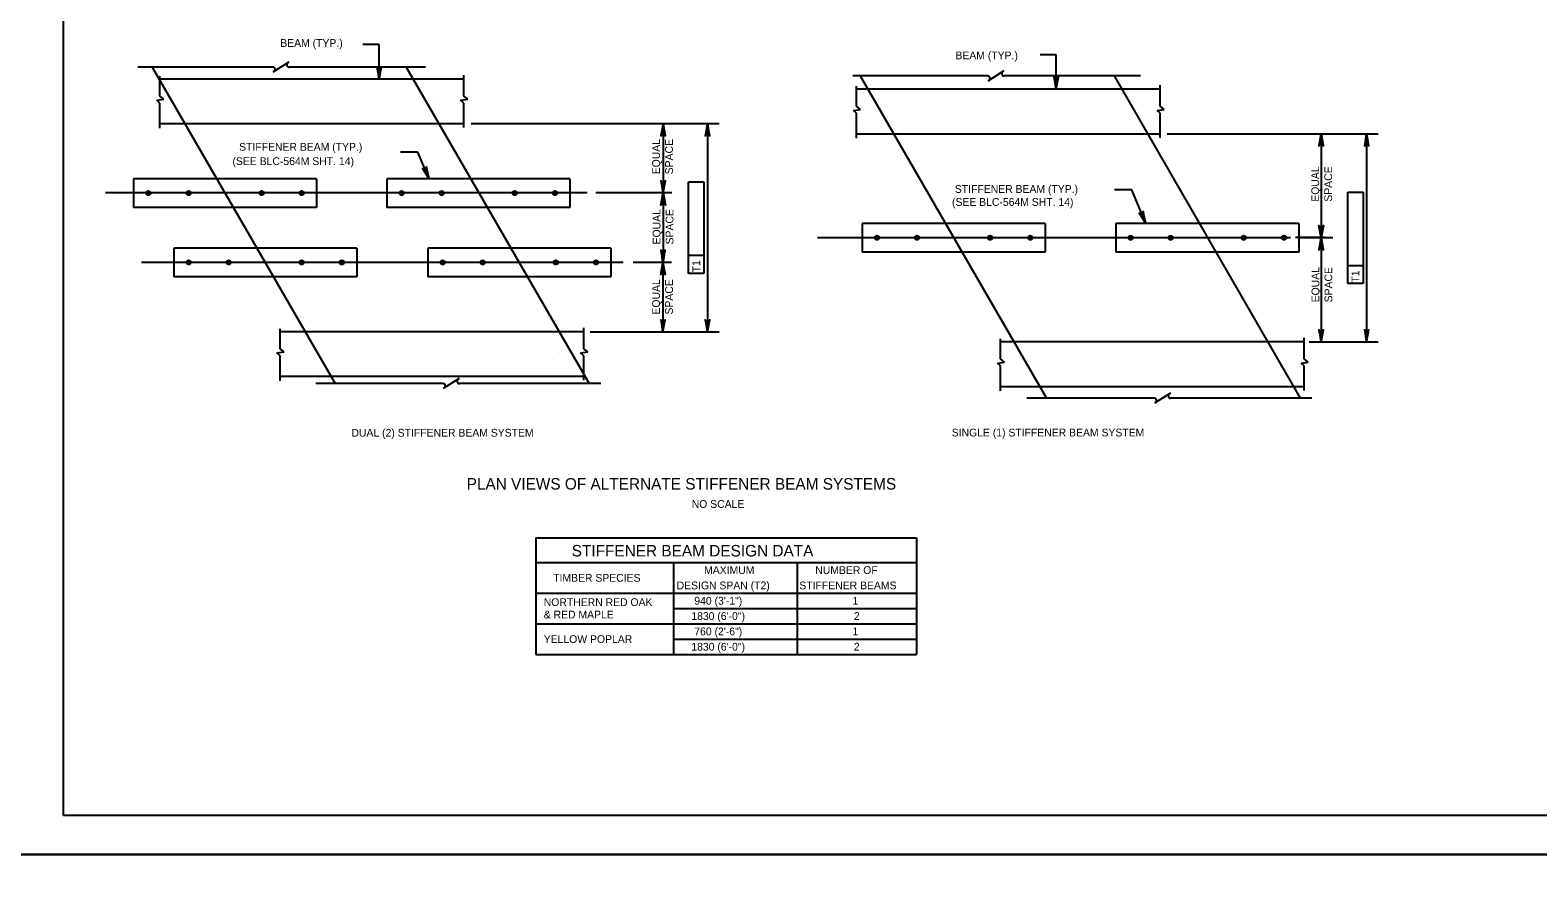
# Model space of a CAD drawing. Extents: x 638175 to 640495, y 294277 to 298435.
# Drawn here: x 639304 to 639885, y 294864 to 295189 of the extents above; entities that cross this region are included whole.
import ezdxf

# ---------------------------------------------------------------- set-up
doc = ezdxf.new("R2010")
doc.units = 0
for name, color, linetype in [('10', 7, 'Continuous'), ('2', 7, 'Continuous'), ('3', 7, 'Continuous'), ('4', 7, 'Continuous'), ('8', 7, 'Continuous'), ('PLT-BNDY', 7, 'Continuous')]:
    doc.layers.add(name, color=color, linetype=linetype)

msp = doc.modelspace()

# ---------------------------------------------------------------- linework, layer by layer
at = {"layer": '10'}
for p, q in [((639498.49, 294993.49), (639498.49, 294948.52)), ((639498.49, 294993.49), (639645.13, 294993.49)), ((639645.13, 294993.49), (639645.13, 294948.52)), ((639498.49, 294983.95), (639645.13, 294983.95)), ((639551.47, 294983.95), (639551.47, 294948.52)), ((639599.24, 294983.95), (639599.24, 294948.52)), ((639498.49, 294972.14), (639645.13, 294972.14)), ((639551.47, 294966.23), (639645.13, 294966.23)), ((639498.49, 294960.33), (639645.13, 294960.33)), ((639551.47, 294954.42), (639645.13, 294954.42)), ((639498.49, 294948.52), (639645.13, 294948.52))]:
    msp.add_line(p, q, dxfattribs=at)
at = {"layer": '2'}
for p, q in [((639316.46, 294886.46), (639316.46, 295450.46)), ((639350.66, 295174.87), (639421.15, 295052.92)), ((639448.49, 295174.87), (639518.98, 295052.92)), ((639623.5, 295171.46), (639695.29, 295047.27)), ((639721.34, 295171.46), (639793.12, 295047.27)), ((640102.46, 294886.46), (639316.46, 294886.46))]:
    msp.add_line(p, q, dxfattribs=at)
at = {"layer": '3'}
for p, q in [((639397.16, 295174.87), (639345.09, 295174.87)), ((639353.61, 295163.71), (639353.61, 295171.43)), ((639403.31, 295176.81), (639397.15, 295172.94)), ((639455.91, 295174.87), (639403.38, 295174.87)), ((639470.69, 295163.71), (639470.69, 295171.81)), ((639672.71, 295171.46), (639620.63, 295171.46)), ((639678.85, 295173.4), (639672.69, 295169.52)), ((639731.46, 295171.46), (639678.92, 295171.46)), ((639470.69, 295170.24), (639353.61, 295170.24)), ((639622.07, 295159.79), (639622.07, 295167.51)), ((639739.15, 295166.32), (639622.07, 295166.32)), ((639739.15, 295159.79), (639739.15, 295167.88)), ((639352.39, 295162.1), (639355.15, 295162.52)), ((639353.61, 295161), (639352.39, 295162.1)), ((639355.15, 295162.52), (639353.61, 295163.71)), ((639353.61, 295151.39), (639353.61, 295161)), ((639469.47, 295162.1), (639472.23, 295162.52)), ((639470.69, 295161), (639469.47, 295162.1)), ((639472.23, 295162.52), (639470.69, 295163.71)), ((639470.69, 295151.58), (639470.69, 295161)), ((639623.62, 295158.6), (639622.07, 295159.79)), ((639740.69, 295158.6), (639739.15, 295159.79)), ((639620.86, 295158.17), (639623.62, 295158.6)), ((639622.07, 295157.08), (639620.86, 295158.17)), ((639622.07, 295147.47), (639622.07, 295157.08)), ((639737.93, 295158.17), (639740.69, 295158.6)), ((639739.15, 295157.08), (639737.93, 295158.17)), ((639739.15, 295147.66), (639739.15, 295157.08)), ((639353.61, 295153.12), (639470.69, 295153.12)), ((639622.07, 295149.2), (639739.15, 295149.2)), ((639413.98, 295131.85), (639343.41, 295131.85)), ((639343.41, 295131.85), (639343.41, 295120.83)), ((639413.98, 295131.85), (639413.98, 295120.83)), ((639511.57, 295131.85), (639441, 295131.85)), ((639441, 295131.85), (639441, 295120.83)), ((639511.57, 295131.85), (639511.57, 295120.83)), ((639476.37, 295126.37), (639476.37, 295126.37)), ((639413.98, 295120.83), (639343.41, 295120.83)), ((639511.57, 295120.83), (639441, 295120.83)), ((639694.8, 295114.65), (639624.22, 295114.65)), ((639624.22, 295114.65), (639624.22, 295103.62)), ((639694.8, 295114.65), (639694.8, 295103.62)), ((639721.97, 295114.65), (639721.97, 295103.62)), ((639792.54, 295114.65), (639721.97, 295114.65)), ((639792.54, 295114.65), (639792.54, 295103.62)), ((639429.46, 295105.1), (639358.89, 295105.1)), ((639358.89, 295105.1), (639358.89, 295094.07)), ((639429.46, 295105.1), (639429.46, 295094.07)), ((639456.81, 295105.1), (639456.81, 295094.07)), ((639527.38, 295105.1), (639456.81, 295105.1)), ((639527.38, 295105.1), (639527.38, 295094.07)), ((639694.8, 295103.62), (639624.22, 295103.62)), ((639792.54, 295103.62), (639721.97, 295103.62)), ((639492.18, 295099.62), (639492.18, 295099.62)), ((639429.46, 295094.07), (639358.89, 295094.07)), ((639527.38, 295094.07), (639456.81, 295094.07)), ((639399.88, 295066.33), (639399.88, 295074.05)), ((639516.96, 295072.86), (639399.88, 295072.86)), ((639516.96, 295066.33), (639516.96, 295074.43)), ((639677.58, 295062.41), (639677.58, 295070.13)), ((639794.66, 295068.94), (639677.58, 295068.94)), ((639794.66, 295062.41), (639794.66, 295070.51)), ((639398.66, 295064.71), (639401.42, 295065.14)), ((639399.88, 295063.62), (639398.66, 295064.71)), ((639401.42, 295065.14), (639399.88, 295066.33)), ((639399.88, 295054.01), (639399.88, 295063.62)), ((639515.74, 295064.71), (639518.49, 295065.14)), ((639516.96, 295063.62), (639515.74, 295064.71)), ((639518.49, 295065.14), (639516.96, 295066.33)), ((639516.96, 295054.2), (639516.96, 295063.62)), ((639676.37, 295060.79), (639679.12, 295061.22)), ((639679.12, 295061.22), (639677.58, 295062.41)), ((639793.44, 295060.79), (639796.2, 295061.22)), ((639796.2, 295061.22), (639794.66, 295062.41)), ((639399.88, 295055.74), (639516.96, 295055.74)), ((639677.58, 295059.7), (639676.37, 295060.79)), ((639677.58, 295050.09), (639677.58, 295059.7)), ((639794.66, 295059.7), (639793.44, 295060.79)), ((639794.66, 295050.28), (639794.66, 295059.7)), ((639462.78, 295052.92), (639413.63, 295052.92)), ((639468.92, 295054.86), (639462.77, 295050.99)), ((639523.48, 295052.92), (639468.99, 295052.92)), ((639677.58, 295051.82), (639794.66, 295051.82)), ((639736.92, 295047.27), (639687.77, 295047.27)), ((639743.06, 295049.21), (639736.9, 295045.34)), ((639797.62, 295047.27), (639743.13, 295047.27))]:
    msp.add_line(p, q, dxfattribs=at)
for centre, radius in [((639349.17, 295126.34), 0.833), ((639349.17, 295126.34), 0.738), ((639349.17, 295126.34), 0.625), ((639349.17, 295126.34), 0.417), ((639349.17, 295126.34), 0.208), ((639364.62, 295126.34), 0.833), ((639364.62, 295126.34), 0.738), ((639364.62, 295126.34), 0.625), ((639364.62, 295126.34), 0.417), ((639364.62, 295126.34), 0.208), ((639392.77, 295126.34), 0.833), ((639392.77, 295126.34), 0.738), ((639392.77, 295126.34), 0.625), ((639392.77, 295126.34), 0.417), ((639392.77, 295126.34), 0.208), ((639408.22, 295126.34), 0.833), ((639408.22, 295126.34), 0.738), ((639408.22, 295126.34), 0.625), ((639408.22, 295126.34), 0.417), ((639408.22, 295126.34), 0.208), ((639446.75, 295126.34), 0.833), ((639446.75, 295126.34), 0.738), ((639446.75, 295126.34), 0.625), ((639446.75, 295126.34), 0.417), ((639446.75, 295126.34), 0.208), ((639462.21, 295126.34), 0.833), ((639462.21, 295126.34), 0.738), ((639462.21, 295126.34), 0.625), ((639462.21, 295126.34), 0.417), ((639462.21, 295126.34), 0.208), ((639490.36, 295126.34), 0.833), ((639490.36, 295126.34), 0.738), ((639490.36, 295126.34), 0.625), ((639490.36, 295126.34), 0.417), ((639490.36, 295126.34), 0.208), ((639505.81, 295126.34), 0.833), ((639505.81, 295126.34), 0.738), ((639505.81, 295126.34), 0.625), ((639505.81, 295126.34), 0.417), ((639505.81, 295126.34), 0.208), ((639629.98, 295109.14), 0.833), ((639629.98, 295109.14), 0.738), ((639629.98, 295109.14), 0.625), ((639629.98, 295109.14), 0.417), ((639629.98, 295109.14), 0.208), ((639645.43, 295109.14), 0.833), ((639645.43, 295109.14), 0.738), ((639645.43, 295109.14), 0.625), ((639645.43, 295109.14), 0.417), ((639645.43, 295109.14), 0.208), ((639673.58, 295109.14), 0.833), ((639673.58, 295109.14), 0.738), ((639673.58, 295109.14), 0.625), ((639673.58, 295109.14), 0.417), ((639673.58, 295109.14), 0.208), ((639689.04, 295109.14), 0.833), ((639689.04, 295109.14), 0.738), ((639689.04, 295109.14), 0.625), ((639689.04, 295109.14), 0.417), ((639689.04, 295109.14), 0.208), ((639727.73, 295109.14), 0.833), ((639727.73, 295109.14), 0.738), ((639727.73, 295109.14), 0.625), ((639727.73, 295109.14), 0.417), ((639727.73, 295109.14), 0.208), ((639743.18, 295109.14), 0.833), ((639743.18, 295109.14), 0.738), ((639743.18, 295109.14), 0.625), ((639743.18, 295109.14), 0.417), ((639743.18, 295109.14), 0.208), ((639771.33, 295109.14), 0.833), ((639771.33, 295109.14), 0.738), ((639771.33, 295109.14), 0.625), ((639771.33, 295109.14), 0.417), ((639771.33, 295109.14), 0.208), ((639786.79, 295109.14), 0.833), ((639786.79, 295109.14), 0.738), ((639786.79, 295109.14), 0.625), ((639786.79, 295109.14), 0.417), ((639786.79, 295109.14), 0.208), ((639364.65, 295099.59), 0.833), ((639364.65, 295099.59), 0.738), ((639364.65, 295099.59), 0.625), ((639364.65, 295099.59), 0.417), ((639364.65, 295099.59), 0.208), ((639380.1, 295099.59), 0.833), ((639380.1, 295099.59), 0.738), ((639380.1, 295099.59), 0.625), ((639380.1, 295099.59), 0.417), ((639380.1, 295099.59), 0.208), ((639408.25, 295099.59), 0.833), ((639408.25, 295099.59), 0.738), ((639408.25, 295099.59), 0.625), ((639408.25, 295099.59), 0.417), ((639408.25, 295099.59), 0.208), ((639423.7, 295099.59), 0.833), ((639423.7, 295099.59), 0.738), ((639423.7, 295099.59), 0.625), ((639423.7, 295099.59), 0.417), ((639423.7, 295099.59), 0.208), ((639462.56, 295099.59), 0.833), ((639462.56, 295099.59), 0.738), ((639462.56, 295099.59), 0.625), ((639462.56, 295099.59), 0.417), ((639462.56, 295099.59), 0.208), ((639478.02, 295099.59), 0.833), ((639478.02, 295099.59), 0.738), ((639478.02, 295099.59), 0.625), ((639478.02, 295099.59), 0.417), ((639478.02, 295099.59), 0.208), ((639506.17, 295099.59), 0.833), ((639506.17, 295099.59), 0.738), ((639506.17, 295099.59), 0.625), ((639506.17, 295099.59), 0.417), ((639506.17, 295099.59), 0.208), ((639521.62, 295099.59), 0.833), ((639521.62, 295099.59), 0.738), ((639521.62, 295099.59), 0.625), ((639521.62, 295099.59), 0.417), ((639521.62, 295099.59), 0.208)]:
    msp.add_circle(centre, radius, dxfattribs=at)
for centre, start, end in [((639397.08, 295173.97), 302.13276, 84.67141), ((639403.38, 295175.78), 120, 270), ((639672.62, 295170.55), 302.13276, 84.67141), ((639678.92, 295172.37), 120, 270), ((639462.69, 295052.02), 302.13276, 84.67141), ((639468.99, 295053.83), 120, 270), ((639736.83, 295046.37), 302.13276, 84.67141), ((639743.13, 295048.18), 120, 270)]:
    msp.add_arc(centre, 0.909, start, end, dxfattribs=at)
at = {"layer": '4'}
for p, q in [((639438.1, 295183.58), (639431.85, 295183.58)), ((639699.05, 295179.66), (639692.83, 295179.66)), ((639473.5, 295153.12), (639558.68, 295153.12)), ((639530.88, 295153.12), (639569.12, 295153.12)), ((639534.7, 295153.12), (639549.76, 295153.12)), ((639547.54, 295153.12), (639547.54, 295126.37)), ((639564.62, 295153.12), (639564.62, 295072.86)), ((639741.74, 295149.2), (639805.67, 295149.2)), ((639792.18, 295149.2), (639823.18, 295149.2)), ((639801.17, 295149.2), (639801.17, 295109.17)), ((639818.68, 295149.2), (639818.68, 295068.94)), ((639453.02, 295142.16), (639446.35, 295142.16)), ((639518.22, 295126.37), (639332.57, 295126.37)), ((639550.91, 295126.37), (639521.54, 295126.37)), ((639547.54, 295126.37), (639547.54, 295102.57)), ((639557.33, 295130.66), (639563.24, 295130.66)), ((639557.33, 295102.83), (639557.33, 295130.66)), ((639563.24, 295130.66), (639563.24, 295095.36)), ((639728.16, 295127.62), (639721.46, 295127.62)), ((639811.39, 295126.74), (639817.29, 295126.74)), ((639811.39, 295098.91), (639811.39, 295126.74)), ((639817.29, 295126.74), (639817.29, 295091.44)), ((639789.34, 295109.14), (639607.06, 295109.14)), ((639802.67, 295109.17), (639791.3, 295109.17)), ((639792.18, 295109.17), (639805.67, 295109.17)), ((639801.17, 295109.17), (639801.17, 295068.94)), ((639557.33, 295095.36), (639557.33, 295102.83)), ((639563.24, 295102.25), (639557.33, 295102.25)), ((639532.08, 295099.58), (639346.43, 295099.58)), ((639550.72, 295099.62), (639536.04, 295099.62)), ((639547.48, 295096.66), (639547.48, 295072.86)), ((639811.39, 295091.44), (639811.39, 295098.91)), ((639817.29, 295098.33), (639811.39, 295098.33)), ((639563.24, 295095.36), (639557.33, 295095.36)), ((639817.29, 295091.44), (639811.39, 295091.44)), ((639519.42, 295072.86), (639569.12, 295072.86)), ((639540.99, 295072.86), (639549.37, 295072.86)), ((639796.48, 295068.94), (639823.18, 295068.94))]:
    msp.add_line(p, q, dxfattribs=at)
for points in [[(639438.1, 295170.24), (639438.1, 295183.58)], [(639699.05, 295166.32), (639699.05, 295179.66)], [(639438.1, 295170.24), (639438.97, 295174.9), (639438.73, 295174.55), (639438.41, 295174.36), (639438.1, 295174.31), (639437.79, 295174.36), (639437.48, 295174.55), (639437.23, 295174.9), (639438.1, 295170.24), (639437.48, 295174.55), (639437.79, 295174.36), (639438.1, 295170.24), (639438.1, 295174.31), (639438.41, 295174.36), (639438.1, 295170.24), (639438.73, 295174.55)], [(639699.05, 295166.32), (639699.92, 295170.98), (639699.67, 295170.62), (639699.36, 295170.44), (639699.05, 295170.38), (639698.74, 295170.44), (639698.42, 295170.62), (639698.18, 295170.98), (639699.05, 295166.32), (639698.42, 295170.62), (639698.74, 295170.44), (639699.05, 295166.32), (639699.05, 295170.38), (639699.36, 295170.44), (639699.05, 295166.32), (639699.67, 295170.62)], [(639547.54, 295153.12), (639546.67, 295148.46), (639546.92, 295148.82), (639547.23, 295149), (639547.54, 295149.06), (639547.85, 295149), (639548.17, 295148.82), (639548.41, 295148.46), (639547.54, 295153.12), (639548.17, 295148.82), (639547.85, 295149), (639547.54, 295153.12), (639547.54, 295149.06), (639547.23, 295149), (639547.54, 295153.12), (639546.92, 295148.82)], [(639564.62, 295153.12), (639563.75, 295148.46), (639563.99, 295148.82), (639564.31, 295149), (639564.62, 295149.06), (639564.93, 295149), (639565.24, 295148.82), (639565.49, 295148.46), (639564.62, 295153.12), (639565.24, 295148.82), (639564.93, 295149), (639564.62, 295153.12), (639564.62, 295149.06), (639564.31, 295149), (639564.62, 295153.12), (639563.99, 295148.82)], [(639801.17, 295149.2), (639800.3, 295144.54), (639800.54, 295144.9), (639800.86, 295145.08), (639801.17, 295145.14), (639801.48, 295145.08), (639801.79, 295144.9), (639802.04, 295144.54), (639801.17, 295149.2), (639801.79, 295144.9), (639801.48, 295145.08), (639801.17, 295149.2), (639801.17, 295145.14), (639800.86, 295145.08), (639801.17, 295149.2), (639800.54, 295144.9)], [(639818.68, 295149.2), (639817.8, 295144.54), (639818.05, 295144.9), (639818.36, 295145.08), (639818.68, 295145.14), (639818.99, 295145.08), (639819.3, 295144.9), (639819.55, 295144.54), (639818.68, 295149.2), (639819.3, 295144.9), (639818.99, 295145.08), (639818.68, 295149.2), (639818.68, 295145.14), (639818.36, 295145.08), (639818.68, 295149.2), (639818.05, 295144.9)], [(639457.33, 295131.85), (639453.02, 295142.16)], [(639457.33, 295131.85), (639456.34, 295136.48), (639456.25, 295136.06), (639456.03, 295135.77), (639455.76, 295135.6), (639455.45, 295135.53), (639455.09, 295135.58), (639454.73, 295135.81), (639457.33, 295131.85), (639455.09, 295135.58), (639455.45, 295135.53), (639457.33, 295131.85), (639455.76, 295135.6), (639456.03, 295135.77), (639457.33, 295131.85), (639456.25, 295136.06)], [(639547.54, 295126.37), (639548.41, 295131.03), (639548.17, 295130.67), (639547.85, 295130.48), (639547.54, 295130.43), (639547.23, 295130.48), (639546.92, 295130.67), (639546.67, 295131.03), (639547.54, 295126.37), (639546.92, 295130.67), (639547.23, 295130.48), (639547.54, 295126.37), (639547.54, 295130.43), (639547.85, 295130.48), (639547.54, 295126.37), (639548.17, 295130.67)], [(639547.54, 295126.37), (639548.41, 295121.71), (639548.17, 295122.07), (639547.85, 295122.25), (639547.54, 295122.31), (639547.23, 295122.25), (639546.92, 295122.07), (639546.67, 295121.71), (639547.54, 295126.37), (639546.92, 295122.07), (639547.23, 295122.25), (639547.54, 295126.37), (639547.54, 295122.31), (639547.85, 295122.25), (639547.54, 295126.37), (639548.17, 295122.07)], [(639733.59, 295114.65), (639728.16, 295127.62)], [(639733.59, 295114.65), (639732.59, 295119.28), (639732.5, 295118.86), (639732.29, 295118.57), (639732.02, 295118.39), (639731.71, 295118.32), (639731.35, 295118.37), (639730.98, 295118.61), (639733.59, 295114.65), (639731.35, 295118.37), (639731.71, 295118.32), (639733.59, 295114.65), (639732.02, 295118.39), (639732.29, 295118.57), (639733.59, 295114.65), (639732.5, 295118.86)], [(639801.17, 295109.17), (639800.3, 295113.83), (639800.54, 295113.47), (639800.86, 295113.28), (639801.17, 295113.23), (639801.48, 295113.28), (639801.79, 295113.47), (639802.04, 295113.83), (639801.17, 295109.17), (639801.79, 295113.47), (639801.48, 295113.28), (639801.17, 295109.17), (639801.17, 295113.23), (639800.86, 295113.28), (639801.17, 295109.17), (639800.54, 295113.47)], [(639801.17, 295109.17), (639800.3, 295104.51), (639800.54, 295104.86), (639800.86, 295105.05), (639801.17, 295105.1), (639801.48, 295105.05), (639801.79, 295104.86), (639802.04, 295104.51), (639801.17, 295109.17), (639801.79, 295104.86), (639801.48, 295105.05), (639801.17, 295109.17), (639801.17, 295105.1), (639800.86, 295105.05), (639801.17, 295109.17), (639800.54, 295104.86)], [(639547.48, 295099.62), (639548.35, 295104.28), (639548.1, 295103.92), (639547.79, 295103.73), (639547.48, 295103.68), (639547.17, 295103.73), (639546.85, 295103.92), (639546.61, 295104.28), (639547.48, 295099.62), (639546.85, 295103.92), (639547.17, 295103.73), (639547.48, 295099.62), (639547.48, 295103.68), (639547.79, 295103.73), (639547.48, 295099.62), (639548.1, 295103.92)], [(639547.48, 295099.62), (639548.35, 295094.96), (639548.1, 295095.31), (639547.79, 295095.5), (639547.48, 295095.55), (639547.17, 295095.5), (639546.85, 295095.31), (639546.61, 295094.96), (639547.48, 295099.62), (639546.85, 295095.31), (639547.17, 295095.5), (639547.48, 295099.62), (639547.48, 295095.55), (639547.79, 295095.5), (639547.48, 295099.62), (639548.1, 295095.31)], [(639547.48, 295072.86), (639548.35, 295077.52), (639548.1, 295077.17), (639547.79, 295076.98), (639547.48, 295076.93), (639547.17, 295076.98), (639546.85, 295077.17), (639546.61, 295077.52), (639547.48, 295072.86), (639546.85, 295077.17), (639547.17, 295076.98), (639547.48, 295072.86), (639547.48, 295076.93), (639547.79, 295076.98), (639547.48, 295072.86), (639548.1, 295077.17)], [(639564.62, 295072.86), (639565.49, 295077.52), (639565.24, 295077.17), (639564.93, 295076.98), (639564.62, 295076.93), (639564.31, 295076.98), (639563.99, 295077.17), (639563.75, 295077.52), (639564.62, 295072.86), (639563.99, 295077.17), (639564.31, 295076.98), (639564.62, 295072.86), (639564.62, 295076.93), (639564.93, 295076.98), (639564.62, 295072.86), (639565.24, 295077.17)], [(639801.17, 295068.94), (639802.04, 295073.6), (639801.79, 295073.24), (639801.48, 295073.06), (639801.17, 295073.01), (639800.86, 295073.06), (639800.54, 295073.24), (639800.3, 295073.6), (639801.17, 295068.94), (639800.54, 295073.24), (639800.86, 295073.06), (639801.17, 295068.94), (639801.17, 295073.01), (639801.48, 295073.06), (639801.17, 295068.94), (639801.79, 295073.24)], [(639818.68, 295068.94), (639819.55, 295073.6), (639819.3, 295073.24), (639818.99, 295073.06), (639818.68, 295073.01), (639818.36, 295073.06), (639818.05, 295073.24), (639817.8, 295073.6), (639818.68, 295068.94), (639818.05, 295073.24), (639818.36, 295073.06), (639818.68, 295068.94), (639818.68, 295073.01), (639818.99, 295073.06), (639818.68, 295068.94), (639819.3, 295073.24)]]:
    msp.add_lwpolyline(points, dxfattribs=at)
for points in [[(639438.1, 295170.24), (639438.07, 295170.36), (639438.13, 295170.36)], [(639699.05, 295166.32), (639699.02, 295166.44), (639699.08, 295166.44)], [(639801.67, 295146.2), (639800.67, 295146.2), (639801.17, 295149.2)], [(639819.18, 295146.2), (639818.18, 295146.2), (639818.68, 295149.2)], [(639457.33, 295131.85), (639457.26, 295131.95), (639457.32, 295131.97)], [(639733.59, 295114.65), (639733.52, 295114.75), (639733.57, 295114.77)], [(639801.67, 295112.17), (639800.67, 295112.17), (639801.17, 295109.17)], [(639801.67, 295106.17), (639800.67, 295106.17), (639801.17, 295109.17)], [(639548.03, 295102.57), (639547.05, 295102.57), (639547.54, 295099.62)], [(639547.97, 295096.66), (639546.99, 295096.66), (639547.48, 295099.62)], [(639547.97, 295075.82), (639546.99, 295075.82), (639547.48, 295072.86)], [(639565.12, 295075.86), (639564.12, 295075.86), (639564.62, 295072.86)], [(639801.67, 295072.13), (639800.67, 295072.13), (639801.17, 295069.13)], [(639819.18, 295071.94), (639818.18, 295071.94), (639818.68, 295068.94)]]:
    msp.add_lwpolyline(points, close=True, dxfattribs=at)
at = {"layer": '8'}
for p, q in [((639460.39, 295162.38), (639460.39, 295162.38)), ((639460.41, 295162.35), (639460.41, 295162.35)), ((639476.37, 295126.37), (639476.37, 295126.37)), ((639492.18, 295099.62), (639492.18, 295099.62)), ((639507.46, 295064.97), (639507.46, 295064.97))]:
    msp.add_line(p, q, dxfattribs=at)
at = {"layer": 'PLT-BNDY'}
for points in [[(639276.46, 295465.46), (640117.46, 295465.46), (640117.46, 294871.46), (639276.46, 294871.46)], [(639276.46, 294871.46), (640117.46, 294871.46), (640117.46, 294277.46), (639276.46, 294277.46)]]:
    msp.add_lwpolyline(points, close=True, dxfattribs=at)

# ---------------------------------------------------------------- texts
at = {"layer": '4'}
for s, height, p in [('BEAM (TYP.)', 3, (639399.97, 295182.68)), ('BEAM (TYP.)', 3, (639660.19, 295177.9)), ('STIFFENER BEAM (TYP.)', 3, (639384.12, 295142.65)), ('(SEE BLC-564M SHT. 14)', 3, (639381.56, 295137.13)), ('STIFFENER BEAM (TYP.)', 3, (639659.97, 295126.41)), ('(SEE BLC-564M SHT. 14)', 3, (639658.87, 295121.4)), ('DUAL (2) STIFFENER BEAM SYSTEM', 3, (639427.4, 295032.46)), ('SINGLE (1) STIFFENER BEAM SYSTEM', 3, (639658.76, 295032.54)), ('PLAN VIEWS OF ALTERNATE STIFFENER BEAM SYSTEMS', 4.4292, (639471.81, 295012.06)), ('NO SCALE', 3, (639558.56, 295005.01)), ('STIFFENER BEAM DESIGN DATA', 4.4292, (639512.31, 294986.28)), ('TIMBER SPECIES', 3, (639505.16, 294976.54)), ('MAXIMUM', 3, (639563.33, 294979.52)), ('NUMBER OF ', 3, (639606.16, 294979.52)), ('DESIGN SPAN (T2)', 3, (639552.74, 294973.62)), ('STIFFENER BEAMS', 3, (639600.03, 294973.62)), ('NORTHERN RED OAK', 3, (639501.52, 294967.17)), ('940 (3\'-1")', 3, (639559.54, 294967.71)), ('1', 3, (639620.52, 294967.71)), ('& RED MAPLE', 3, (639501.52, 294962.39)), ('1830 (6\'-0")', 3, (639558.4, 294961.81)), ('2', 3, (639621.04, 294961.81)), ('760 (2\'-6")', 3, (639559.54, 294955.9)), ('1', 3, (639620.52, 294955.9)), ('YELLOW POPLAR', 3, (639501.52, 294952.92)), ('1830 (6\'-0")', 3, (639558.4, 294949.99)), ('2', 3, (639621.04, 294949.99))]:
    msp.add_text(s, height=height, dxfattribs=at).set_placement(p)
for p in [(639561.81, 295095.79), (639815.86, 295091.87)]:
    msp.add_text('T1', height=3, rotation=90, dxfattribs=at).set_placement(p)
at = {"layer": '8'}
for s, p in [('EQUAL ', (639546.31, 295133.57)), ('SPACE', (639551.31, 295133.57)), ('EQUAL ', (639800.36, 295123.02)), ('SPACE', (639805.36, 295123.02)), ('EQUAL ', (639546.5, 295106.55)), ('SPACE', (639551.5, 295106.55)), ('EQUAL ', (639800.44, 295084.22)), ('SPACE', (639805.44, 295084.22)), ('EQUAL ', (639546.31, 295079.53)), ('SPACE', (639551.31, 295079.53))]:
    msp.add_text(s, height=3, rotation=89.9708, dxfattribs=at).set_placement(p)

doc.saveas('drawing.dxf')
